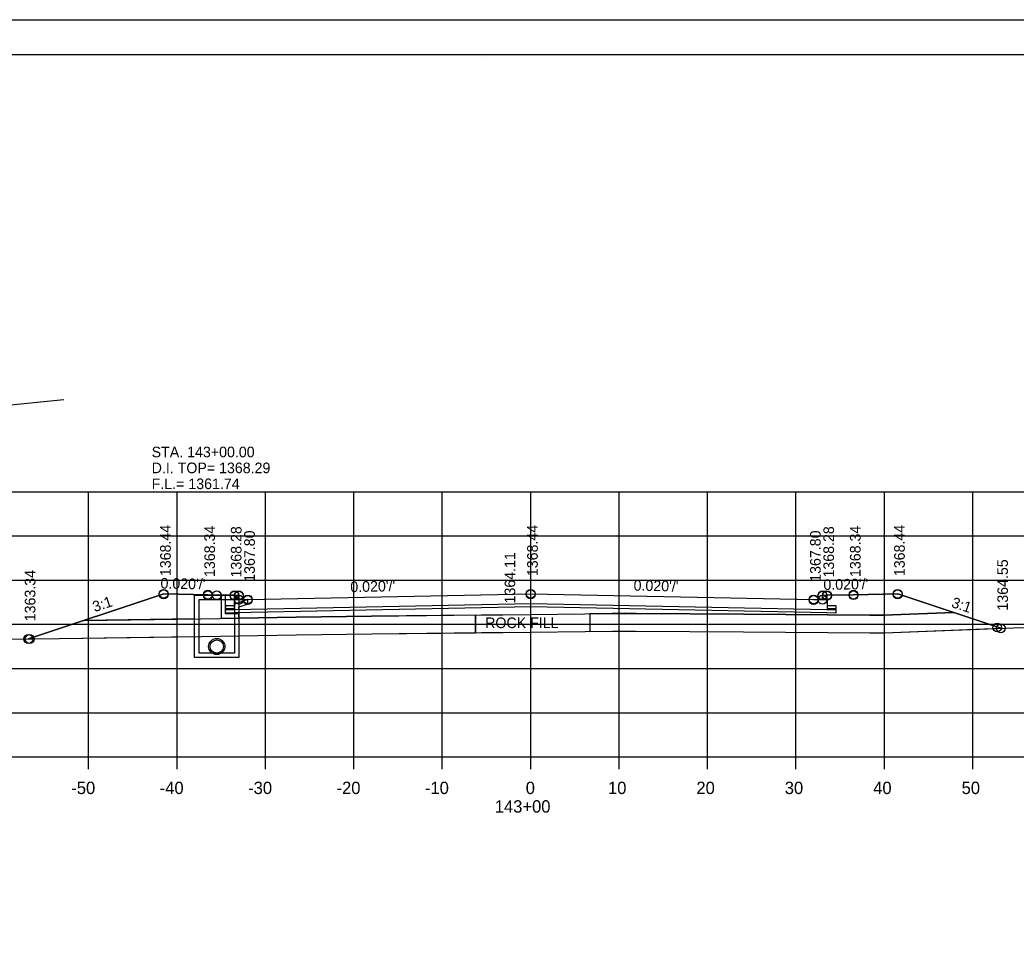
# Model space of a CAD drawing. Extents: x 1374311 to 1383814, y 384102 to 406278.
# Drawn here: x 1381570.9 to 1381683.6, y 389765.2 to 389871.4 of the extents above; entities that cross this region are included whole.
import ezdxf

# ---------------------------------------------------------------- set-up
doc = ezdxf.new("R2010")
doc.units = 0
for name, color, linetype in [('R_Axis', 7, 'Continuous'), ('R_Axis Annot', 7, 'Continuous'), ('R_Border', 7, 'Continuous'), ('R_Exist Surface', 7, 'Continuous'), ('R_Fin Surface', 7, 'Continuous'), ('R_Grid', 7, 'Continuous'), ('R_No Plot', 7, 'Continuous'), ('R_Water', 7, 'Continuous'), ('R_Water Annot', 7, 'Continuous'), ('R_Xsect Elev', 7, 'Continuous'), ('R_Xsect Slope', 7, 'Continuous')]:
    doc.layers.add(name, color=color, linetype=linetype)

msp = doc.modelspace()

# ---------------------------------------------------------------- linework, layer by layer
at = {"layer": 'R_Axis'}
for p, q in [((1381488.66, 389788.03), (1381768.66, 389788.03)), ((1381578.66, 389786.63), (1381578.66, 389788.03)), ((1381588.66, 389786.63), (1381588.66, 389788.03)), ((1381598.66, 389786.63), (1381598.66, 389788.03)), ((1381608.66, 389786.63), (1381608.66, 389788.03)), ((1381618.66, 389786.63), (1381618.66, 389788.03)), ((1381628.66, 389786.63), (1381628.66, 389788.03)), ((1381638.66, 389786.63), (1381638.66, 389788.03)), ((1381648.66, 389786.63), (1381648.66, 389788.03)), ((1381658.66, 389786.63), (1381658.66, 389788.03)), ((1381668.66, 389786.63), (1381668.66, 389788.03)), ((1381678.66, 389786.63), (1381678.66, 389788.03))]:
    msp.add_line(p, q, dxfattribs=at)
at = {"layer": 'R_Border'}
for p, q in [((1381470.66, 389867.49), (1381786.84, 389867.49)), ((1381623.18, 389867.23), (1381623.18, 389867.23)), ((1381623.18, 389867.23), (1381623.18, 389867.23))]:
    msp.add_line(p, q, dxfattribs=at)
at = {"layer": 'R_Exist Surface'}
msp.add_lwpolyline([(1381569.49, 389801.34), (1381575.34, 389801.43), (1381591.37, 389801.66), (1381602.15, 389801.83), (1381610.7, 389801.96), (1381623.1, 389802.09), (1381625.5, 389802.11), (1381637.91, 389802.25), (1381640.57, 389802.25), (1381652.74, 389802.17), (1381667, 389802.08), (1381668.65, 389802.07), (1381683.28, 389802.64), (1381688.1, 389802.77), (1381705.22, 389803.29), (1381711.36, 389803.47), (1381725.24, 389803.78), (1381746.33, 389804.31), (1381748.44, 389804.34), (1381748.91, 389804.35), (1381762.45, 389804.37), (1381766.01, 389804.43), (1381768.66, 389804.44)], dxfattribs=at)
msp.add_circle((1381593.15, 389800.52), 0.917, dxfattribs=at)
at = {"layer": 'R_Fin Surface'}
for p, q in [((1381590.65, 389803.65), (1381578.13, 389803.47)), ((1381590.65, 389801.65), (1381590.65, 389803.65)), ((1381622.43, 389804.08), (1381610.67, 389803.96)), ((1381622.43, 389804.08), (1381622.43, 389802.08)), ((1381622.43, 389802.08), (1381622.43, 389804.08)), ((1381635.34, 389804.22), (1381635.34, 389802.22)), ((1381635.34, 389804.22), (1381635.34, 389802.22)), ((1381578.13, 389803.47), (1381571.84, 389801.37)), ((1381571.84, 389801.37), (1381575.34, 389801.43)), ((1381575.34, 389801.43), (1381590.65, 389801.65)), ((1381595.65, 389801.73), (1381602.15, 389801.83)), ((1381602.15, 389801.83), (1381610.7, 389801.96)), ((1381610.7, 389801.96), (1381622.43, 389802.08)), ((1381635.34, 389802.22), (1381637.91, 389802.25)), ((1381652.74, 389802.17), (1381667, 389802.08))]:
    msp.add_line(p, q, dxfattribs=at)
for points in [[(1381571.84, 389801.37), (1381587.15, 389806.48), (1381592.15, 389806.38), (1381595.15, 389806.32), (1381595.65, 389806.32), (1381595.66, 389805.82), (1381596.66, 389805.84), (1381628.66, 389806.48), (1381660.66, 389805.84), (1381661.66, 389805.82), (1381661.67, 389806.32), (1381662.17, 389806.32), (1381665.17, 389806.38), (1381670.17, 389806.48), (1381681.84, 389802.58)], [(1381662.17, 389805.96), (1381662.18, 389804.81), (1381663.18, 389804.8), (1381663.17, 389804.3), (1381662.17, 389804.32), (1381628.66, 389804.99), (1381595.15, 389804.32), (1381594.15, 389804.3), (1381594.16, 389804.8), (1381595.16, 389804.81), (1381595.15, 389805.96)], [(1381578.13, 389803.47), (1381591.34, 389803.66), (1381602.12, 389803.83), (1381610.67, 389803.96), (1381623.08, 389804.09), (1381625.49, 389804.11), (1381637.89, 389804.25), (1381640.58, 389804.25), (1381652.75, 389804.17), (1381667.02, 389804.08), (1381668.62, 389804.07), (1381676.47, 389804.38)], [(1381610.67, 389803.96), (1381602.12, 389803.83), (1381595.65, 389803.73)], [(1381595.65, 389803.73), (1381595.65, 389803.73), (1381595.65, 389801.73)], [(1381676.47, 389804.38), (1381668.62, 389804.07), (1381667.02, 389804.08), (1381652.75, 389804.17), (1381640.58, 389804.25), (1381637.89, 389804.25), (1381635.34, 389804.22)], [(1381667, 389802.08), (1381668.65, 389802.07), (1381681.84, 389802.58), (1381676.47, 389804.38)], [(1381578.13, 389803.47), (1381578.13, 389803.47)], [(1381637.91, 389802.25), (1381640.57, 389802.25), (1381652.74, 389802.17)]]:
    msp.add_lwpolyline(points, dxfattribs=at)
at = {"layer": 'R_Grid'}
for p, q in [((1381488.66, 389818.03), (1381768.66, 389818.03)), ((1381578.66, 389788.03), (1381578.66, 389818.03)), ((1381588.66, 389788.03), (1381588.66, 389818.03)), ((1381598.66, 389788.03), (1381598.66, 389818.03)), ((1381608.66, 389788.03), (1381608.66, 389818.03)), ((1381618.66, 389788.03), (1381618.66, 389818.03)), ((1381628.66, 389788.03), (1381628.66, 389818.03)), ((1381638.66, 389788.03), (1381638.66, 389818.03)), ((1381648.66, 389788.03), (1381648.66, 389818.03)), ((1381658.66, 389788.03), (1381658.66, 389818.03)), ((1381668.66, 389788.03), (1381668.66, 389818.03)), ((1381678.66, 389788.03), (1381678.66, 389818.03)), ((1381488.66, 389813.03), (1381768.66, 389813.03)), ((1381488.66, 389808.03), (1381768.66, 389808.03)), ((1381488.66, 389803.03), (1381768.66, 389803.03)), ((1381488.66, 389798.03), (1381768.66, 389798.03)), ((1381488.66, 389793.03), (1381768.66, 389793.03)), ((1381488.66, 389788.03), (1381768.66, 389788.03))]:
    msp.add_line(p, q, dxfattribs=at)
at = {"layer": 'R_No Plot'}
msp.add_line((1381458.26, 389871.39), (1381791.59, 389871.39), dxfattribs=at)
for points in [[(1381458.25, 389871.39), (1381791.59, 389871.39), (1381791.59, 389658.05), (1381458.25, 389658.05)], [(1381704.58, 389867.49), (1381704.58, 389857.61), (1381740.31, 389857.61), (1381740.31, 389854.69), (1381763.51, 389854.69), (1381763.51, 389831.48), (1381786.84, 389831.48), (1381786.84, 389662.03), (1381470.66, 389662.03), (1381470.66, 389867.49)], [(1381571.84, 389801.37), (1381575.34, 389801.43), (1381591.37, 389801.66), (1381602.15, 389801.83), (1381610.7, 389801.96), (1381623.1, 389802.09), (1381625.5, 389802.11), (1381637.91, 389802.25), (1381640.57, 389802.25), (1381652.74, 389802.17), (1381667, 389802.08), (1381668.65, 389802.07), (1381681.84, 389802.58), (1381670.17, 389806.48), (1381665.17, 389806.38), (1381662.17, 389806.32), (1381662.18, 389805.17), (1381663.18, 389805.16), (1381663.17, 389804.66), (1381662.17, 389804.68), (1381628.66, 389805.35), (1381595.15, 389804.68), (1381594.15, 389804.66), (1381594.16, 389805.16), (1381595.16, 389805.17), (1381595.15, 389806.32), (1381592.15, 389806.38), (1381587.15, 389806.48)]]:
    msp.add_lwpolyline(points, close=True, dxfattribs=at)
for centre in [(1381587.15, 389806.48), (1381587.15, 389806.48), (1381587.15, 389806.42), (1381592.15, 389806.38), (1381592.15, 389806.38), (1381592.15, 389806.32), (1381593.15, 389806.32), (1381595.15, 389806.32), (1381595.15, 389806.32), (1381595.15, 389806.26), (1381595.65, 389806.32), (1381595.65, 389806.32), (1381595.65, 389806.26), (1381595.66, 389805.82), (1381596.66, 389805.84), (1381596.66, 389805.84), (1381596.66, 389805.78), (1381628.66, 389806.48), (1381628.66, 389806.48), (1381628.66, 389806.42), (1381660.66, 389805.84), (1381660.66, 389805.84), (1381660.66, 389805.78), (1381661.66, 389805.82), (1381661.67, 389806.32), (1381661.67, 389806.32), (1381661.67, 389806.26), (1381662.17, 389806.32), (1381662.17, 389806.32), (1381662.17, 389806.26), (1381665.17, 389806.38), (1381665.17, 389806.38), (1381665.17, 389806.32), (1381670.17, 389806.48), (1381670.17, 389806.48), (1381670.17, 389806.42), (1381681.42, 389802.67), (1381681.84, 389802.58), (1381681.84, 389802.58), (1381571.84, 389801.37), (1381571.84, 389801.37), (1381571.84, 389801.37), (1381571.84, 389801.37), (1381571.99, 389801.36), (1381571.99, 389801.36)]:
    msp.add_circle(centre, 0.5, dxfattribs=at)
at = {"layer": 'R_Water'}
for p, q in [((1381575.84, 389828.4), (1381565.39, 389827.36)), ((1381590.65, 389806.32), (1381595.4, 389806.32)), ((1381590.65, 389804.82), (1381590.65, 389806.32)), ((1381595.48, 389806.16), (1381595.15, 389805.82)), ((1381595.48, 389806.16), (1381595.4, 389806.32)), ((1381591.15, 389804.82), (1381591.15, 389805.82)), ((1381591.15, 389805.82), (1381595.15, 389805.82)), ((1381596.65, 389805.84), (1381595.15, 389805.32)), ((1381595.15, 389804.82), (1381595.15, 389805.32)), ((1381596.65, 389805.31), (1381595.65, 389804.97)), ((1381595.65, 389804.82), (1381595.65, 389804.97))]:
    msp.add_line(p, q, dxfattribs=at)
for points in [[(1381593.15, 389806.32), (1381595.65, 389806.32), (1381595.65, 389799.27), (1381593.15, 389799.27), (1381590.65, 389799.27), (1381590.65, 389806.32)], [(1381593.15, 389805.82), (1381595.15, 389805.82), (1381595.15, 389799.77), (1381593.15, 389799.77), (1381591.15, 389799.77), (1381591.15, 389805.82)]]:
    msp.add_lwpolyline(points, close=True, dxfattribs=at)
for points in [[(1381593.64, 389806.26), (1381593.64, 389803.73), (1381595.64, 389803.73), (1381595.64, 389804.23), (1381594.14, 389804.23), (1381594.14, 389806.25)], [(1381596.65, 389805.31), (1381596.65, 389805.84)]]:
    msp.add_lwpolyline(points, dxfattribs=at)
msp.add_circle((1381593.15, 389800.52), 0.75, dxfattribs=at)

# ---------------------------------------------------------------- texts
at = {"layer": 'R_Axis Annot'}
for s, p in [('-50', (1381576.7, 389783.83)), ('-40', (1381586.7, 389783.83)), ('-30', (1381596.7, 389783.83)), ('-20', (1381606.7, 389783.83)), ('-10', (1381616.7, 389783.83)), ('0', (1381628.1, 389783.83)), ('10', (1381637.4, 389783.83)), ('20', (1381647.4, 389783.83)), ('30', (1381657.4, 389783.83)), ('40', (1381667.4, 389783.83)), ('50', (1381677.4, 389783.83)), ('143+00', (1381624.6, 389781.73))]:
    msp.add_text(s, height=1.4, dxfattribs=at).set_placement(p)
at = {"layer": 'R_Fin Surface'}
msp.add_text('ROCK FILL', height=1.2, dxfattribs=at).set_placement((1381623.51, 389802.6))
at = {"layer": 'R_Water Annot'}
for s, p in [('STA. 143+00.00', (1381585.79, 389821.92)), ('D.I. TOP= 1368.29', (1381585.79, 389820.12)), ('F.L.= 1361.74', (1381585.79, 389818.32))]:
    msp.add_text(s, height=1.2, dxfattribs=at).set_placement(p)
at = {"layer": 'R_Xsect Elev'}
for s, p in [('1368.44', (1381587.95, 389808.48)), ('1368.34', (1381592.95, 389808.38)), ('1368.28', (1381595.95, 389808.32)), ('1368.44', (1381629.46, 389808.48)), ('1368.28', (1381662.97, 389808.32)), ('1368.34', (1381665.97, 389808.38)), ('1368.44', (1381670.97, 389808.48)), ('1367.80', (1381597.46, 389807.84)), ('1367.80', (1381661.46, 389807.84)), ('1364.11', (1381626.91, 389805.39)), ('1364.55', (1381682.64, 389804.58)), ('1363.34', (1381572.64, 389803.37))]:
    msp.add_text(s, height=1.2, rotation=90, dxfattribs=at).set_placement(p)
at = {"layer": 'R_Xsect Slope'}
for s, rotation, p in [("0.020'/'", 358.8542, (1381586.78, 389807.08)), ("0.020'/'", 1.1458, (1381661.78, 389806.91)), ("0.020'/'", 1.1458, (1381608.27, 389806.67)), ("0.020'/'", 358.8542, (1381640.29, 389806.84)), ('3:1', 18.4349, (1381579.34, 389804.4)), ('3:1', 341.5651, (1381676.16, 389805))]:
    msp.add_text(s, height=1.2, rotation=rotation, dxfattribs=at).set_placement(p)

doc.saveas('drawing.dxf')
